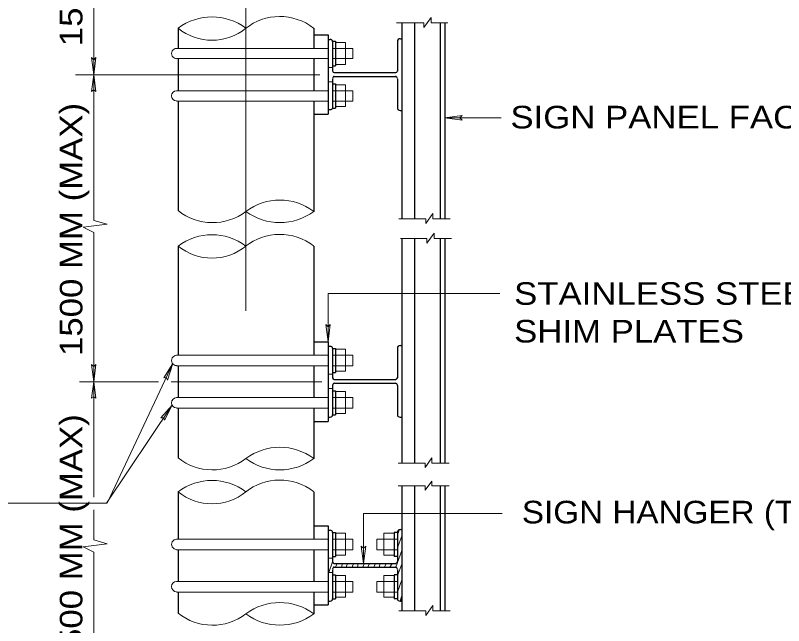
# Model space of a CAD drawing. Extents: x 312601.858 to 312602.699, y 144420.109 to 144420.704.
# Drawn here: x 312602.1613 to 312602.2633, y 144420.5041 to 144420.5851 of the extents above; entities that cross this region are included whole.
import ezdxf
from ezdxf.enums import TextEntityAlignment as Align

# ---------------------------------------------------------------- set-up
doc = ezdxf.new("R2010")
doc.units = 0
doc.header["$LTSCALE"] = 0.0012
doc.linetypes.add('DOT_DASHED', pattern=[7.7, 5, -1.2, 0.3, -1.2])
doc.linetypes.add('MEDIUM_DASHED', pattern=[4.5, 3, -1.5])
doc.layers.add('1', color=7, linetype='Continuous', lineweight=13)
doc.layers.add('2', color=7, linetype='Continuous', lineweight=13)

msp = doc.modelspace()

# ---------------------------------------------------------------- linework, layer by layer
at = {"layer": '1'}
for p, q in [((312602.2155, 144420.5835), (312602.2165, 144420.5848)), ((312602.2165, 144420.5841), (312602.2165, 144420.5848)), ((312602.2119, 144420.5841), (312602.2155, 144420.5841)), ((312602.2155, 144420.5835), (312602.2155, 144420.5841)), ((312602.2165, 144420.5841), (312602.2187, 144420.5841)), ((312602.2028, 144420.5825), (312602.2028, 144420.5736)), ((312602.1827, 144420.5807), (312602.2009, 144420.5807)), ((312602.2051, 144420.5807), (312602.2061, 144420.5807)), ((312602.2061, 144420.5807), (312602.2061, 144420.5794)), ((312602.2009, 144420.5794), (312602.1827, 144420.5794)), ((312602.2061, 144420.5794), (312602.2051, 144420.5794)), ((312602.2038, 144420.5786), (312602.2051, 144420.5786)), ((312602.2028, 144420.5782), (312602.2034, 144420.5782)), ((312602.1693, 144420.5772), (312602.2017, 144420.5772)), ((312602.2028, 144420.5763), (312602.2034, 144420.5763)), ((312602.2038, 144420.5759), (312602.2051, 144420.5759)), ((312602.2051, 144420.573), (312602.2051, 144420.5759)), ((312602.2009, 144420.5751), (312602.1827, 144420.5751)), ((312602.2061, 144420.5751), (312602.2051, 144420.5751)), ((312602.2061, 144420.5737), (312602.2061, 144420.5751)), ((312602.1827, 144420.5737), (312602.2009, 144420.5737)), ((312602.2051, 144420.5737), (312602.2061, 144420.5737)), ((312602.2038, 144420.573), (312602.2051, 144420.573)), ((312602.2258, 144420.5715), (312602.2183, 144420.5715)), ((312602.2122, 144420.5581), (312602.2158, 144420.5581)), ((312602.2158, 144420.5575), (312602.2167, 144420.5588)), ((312602.2158, 144420.5575), (312602.2158, 144420.5581)), ((312602.2167, 144420.5581), (312602.2167, 144420.5588)), ((312602.2167, 144420.5581), (312602.219, 144420.5581)), ((312602.1717, 144420.5563), (312602.1717, 144420.5365)), ((312602.2159, 144420.5549), (312602.2169, 144420.5562)), ((312602.2169, 144420.5555), (312602.2169, 144420.5562)), ((312602.2124, 144420.5555), (312602.2159, 144420.5555)), ((312602.2159, 144420.5549), (312602.2159, 144420.5555)), ((312602.2169, 144420.5555), (312602.2192, 144420.5555)), ((312602.2256, 144420.5482), (312602.2028, 144420.5482)), ((312602.2028, 144420.5482), (312602.2028, 144420.5418)), ((312602.1827, 144420.54), (312602.2009, 144420.54)), ((312602.2051, 144420.54), (312602.2061, 144420.54)), ((312602.2061, 144420.54), (312602.2061, 144420.5386)), ((312602.2009, 144420.5386), (312602.1827, 144420.5386)), ((312602.2061, 144420.5386), (312602.2051, 144420.5386)), ((312602.2028, 144420.5375), (312602.2034, 144420.5375)), ((312602.2038, 144420.5379), (312602.2051, 144420.5379)), ((312602.1698, 144420.5365), (312602.1803, 144420.5365)), ((312602.1717, 144420.5365), (312602.1717, 144420.5212)), ((312602.202, 144420.5365), (312602.182, 144420.5365)), ((312602.2028, 144420.5356), (312602.2034, 144420.5356)), ((312602.2038, 144420.5352), (312602.2051, 144420.5352)), ((312602.2051, 144420.5323), (312602.2051, 144420.5352)), ((312602.2009, 144420.5344), (312602.1827, 144420.5344)), ((312602.2061, 144420.5344), (312602.2051, 144420.5344)), ((312602.2061, 144420.533), (312602.2061, 144420.5344)), ((312602.1827, 144420.533), (312602.2009, 144420.533)), ((312602.2051, 144420.533), (312602.2061, 144420.533)), ((312602.2038, 144420.5323), (312602.2051, 144420.5323)), ((312602.2157, 144420.5251), (312602.2166, 144420.5264)), ((312602.2166, 144420.5257), (312602.2166, 144420.5264)), ((312602.2121, 144420.5257), (312602.2157, 144420.5257)), ((312602.2157, 144420.5251), (312602.2157, 144420.5257)), ((312602.2166, 144420.5257), (312602.2189, 144420.5257)), ((312602.2157, 144420.5221), (312602.2166, 144420.5233)), ((312602.2166, 144420.5227), (312602.2166, 144420.5233)), ((312602.2121, 144420.5227), (312602.2157, 144420.5227)), ((312602.2157, 144420.5221), (312602.2157, 144420.5227)), ((312602.1194, 144420.5204), (312602.1734, 144420.5204)), ((312602.1717, 144420.5195), (312602.1717, 144420.5155)), ((312602.2075, 144420.5124), (312602.2075, 144420.519)), ((312602.2259, 144420.519), (312602.2075, 144420.519)), ((312602.2028, 144420.5174), (312602.2028, 144420.5085)), ((312602.212, 144420.5162), (312602.2123, 144420.5169)), ((312602.1827, 144420.5156), (312602.2009, 144420.5156)), ((312602.2051, 144420.5156), (312602.2061, 144420.5156)), ((312602.2061, 144420.5156), (312602.2061, 144420.5142)), ((312602.2093, 144420.5156), (312602.2093, 144420.5142)), ((312602.2102, 144420.5156), (312602.2093, 144420.5156)), ((312602.212, 144420.5145), (312602.2126, 144420.516)), ((312602.2009, 144420.5142), (312602.1827, 144420.5142)), ((312602.2061, 144420.5142), (312602.2051, 144420.5142)), ((312602.2093, 144420.5142), (312602.2102, 144420.5142)), ((312602.2118, 144420.5119), (312602.2126, 144420.5141)), ((312602.1717, 144420.5139), (312602.1717, 144420.4956)), ((312602.2028, 144420.5131), (312602.2034, 144420.5131)), ((312602.2038, 144420.5135), (312602.2051, 144420.5135)), ((312602.2116, 144420.5135), (312602.2102, 144420.5135)), ((312602.2029, 144420.5112), (312602.2034, 144420.5126)), ((312602.2038, 144420.5119), (312602.204, 144420.5124)), ((312602.2046, 144420.5119), (312602.2047, 144420.5124)), ((312602.2052, 144420.5119), (312602.2054, 144420.5124)), ((312602.206, 144420.5119), (312602.2062, 144420.5124)), ((312602.2067, 144420.5119), (312602.2068, 144420.5124)), ((312602.2074, 144420.5119), (312602.2076, 144420.5124)), ((312602.2081, 144420.5119), (312602.2083, 144420.5124)), ((312602.2089, 144420.5119), (312602.2091, 144420.5124)), ((312602.2096, 144420.5119), (312602.2097, 144420.5124)), ((312602.2103, 144420.5119), (312602.2105, 144420.5124)), ((312602.211, 144420.5119), (312602.2113, 144420.5124)), ((312602.212, 144420.5108), (312602.2126, 144420.5123)), ((312602.2028, 144420.5112), (312602.2034, 144420.5112)), ((312602.2009, 144420.51), (312602.1827, 144420.51)), ((312602.2038, 144420.5108), (312602.2051, 144420.5108)), ((312602.2051, 144420.5079), (312602.2051, 144420.5108)), ((312602.2061, 144420.51), (312602.2051, 144420.51)), ((312602.2061, 144420.5086), (312602.2061, 144420.51)), ((312602.2093, 144420.5086), (312602.2093, 144420.51)), ((312602.2093, 144420.51), (312602.2102, 144420.51)), ((312602.2116, 144420.5108), (312602.2102, 144420.5108)), ((312602.212, 144420.5086), (312602.2126, 144420.5102)), ((312602.1827, 144420.5086), (312602.2009, 144420.5086)), ((312602.2051, 144420.5086), (312602.2061, 144420.5086)), ((312602.2102, 144420.5086), (312602.2093, 144420.5086)), ((312602.2038, 144420.5079), (312602.2051, 144420.5079)), ((312602.2122, 144420.5061), (312602.2158, 144420.5061)), ((312602.2158, 144420.5055), (312602.2167, 144420.5068)), ((312602.2158, 144420.5055), (312602.2158, 144420.5061)), ((312602.2167, 144420.5061), (312602.2167, 144420.5068)), ((312602.2167, 144420.5061), (312602.219, 144420.5061))]:
    msp.add_line(p, q, dxfattribs=at)
at = {"layer": '1', "lineweight": 25}
for p, q in [((312602.1829, 144420.5834), (312602.1829, 144420.5807)), ((312602.2009, 144420.5834), (312602.2009, 144420.5807)), ((312602.2126, 144420.5841), (312602.2126, 144420.5581)), ((312602.2143, 144420.5841), (312602.2143, 144420.5581)), ((312602.2177, 144420.5841), (312602.2177, 144420.5581)), ((312602.2183, 144420.5841), (312602.2183, 144420.5581)), ((312602.2028, 144420.5819), (312602.2031, 144420.5819)), ((312602.2034, 144420.5817), (312602.2034, 144420.5777)), ((312602.2034, 144420.5817), (312602.2038, 144420.5817)), ((312602.2038, 144420.5817), (312602.2038, 144420.5784)), ((312602.212, 144420.5817), (312602.212, 144420.5777)), ((312602.2124, 144420.582), (312602.2126, 144420.582)), ((312602.1829, 144420.5794), (312602.1829, 144420.5751)), ((312602.2009, 144420.5794), (312602.2009, 144420.5751)), ((312602.2034, 144420.5784), (312602.2038, 144420.5784)), ((312602.2036, 144420.5775), (312602.2118, 144420.5775)), ((312602.2034, 144420.5767), (312602.2034, 144420.5728)), ((312602.2036, 144420.577), (312602.2118, 144420.577)), ((312602.212, 144420.5767), (312602.212, 144420.5728)), ((312602.2034, 144420.576), (312602.2038, 144420.576)), ((312602.2038, 144420.576), (312602.2038, 144420.5728)), ((312602.1829, 144420.5737), (312602.1829, 144420.5592)), ((312602.2009, 144420.5737), (312602.2009, 144420.5591)), ((312602.2028, 144420.5726), (312602.2031, 144420.5726)), ((312602.2034, 144420.5728), (312602.2038, 144420.5728)), ((312602.2124, 144420.5725), (312602.2126, 144420.5725)), ((312602.2009, 144420.572), (312602.2028, 144420.572)), ((312602.2126, 144420.5555), (312602.2126, 144420.5257)), ((312602.2143, 144420.5555), (312602.2143, 144420.5257)), ((312602.2177, 144420.5555), (312602.2177, 144420.5257)), ((312602.2183, 144420.5555), (312602.2183, 144420.5257)), ((312602.1829, 144420.5545), (312602.1829, 144420.54)), ((312602.2009, 144420.5545), (312602.2009, 144420.54)), ((312602.2028, 144420.5412), (312602.2031, 144420.5412)), ((312602.2034, 144420.5409), (312602.2034, 144420.537)), ((312602.2034, 144420.5409), (312602.2038, 144420.5409)), ((312602.2038, 144420.5409), (312602.2038, 144420.5377)), ((312602.212, 144420.5409), (312602.212, 144420.537)), ((312602.2124, 144420.5413), (312602.2126, 144420.5413)), ((312602.1829, 144420.5386), (312602.1829, 144420.5344)), ((312602.2009, 144420.5386), (312602.2009, 144420.5344)), ((312602.2034, 144420.5377), (312602.2038, 144420.5377)), ((312602.2036, 144420.5368), (312602.2118, 144420.5368)), ((312602.2034, 144420.536), (312602.2034, 144420.5321)), ((312602.2036, 144420.5363), (312602.2118, 144420.5363)), ((312602.212, 144420.536), (312602.212, 144420.5321)), ((312602.2034, 144420.5353), (312602.2038, 144420.5353)), ((312602.2038, 144420.5353), (312602.2038, 144420.5321)), ((312602.1829, 144420.533), (312602.1829, 144420.5264)), ((312602.2009, 144420.533), (312602.2009, 144420.5263)), ((312602.2028, 144420.5318), (312602.2031, 144420.5318)), ((312602.2034, 144420.5321), (312602.2038, 144420.5321)), ((312602.2124, 144420.5318), (312602.2126, 144420.5318)), ((312602.2009, 144420.5312), (312602.2028, 144420.5312)), ((312602.2126, 144420.5227), (312602.2126, 144420.5061)), ((312602.2143, 144420.5227), (312602.2143, 144420.5061)), ((312602.2177, 144420.5227), (312602.2177, 144420.5061)), ((312602.2183, 144420.5227), (312602.2183, 144420.5061)), ((312602.1829, 144420.5219), (312602.1829, 144420.5156)), ((312602.2009, 144420.5219), (312602.2009, 144420.5156)), ((312602.2028, 144420.5168), (312602.2031, 144420.5168)), ((312602.2034, 144420.5165), (312602.2034, 144420.5126)), ((312602.2034, 144420.5165), (312602.2038, 144420.5165)), ((312602.2038, 144420.5165), (312602.2038, 144420.5133)), ((312602.212, 144420.5165), (312602.2116, 144420.5165)), ((312602.2116, 144420.5165), (312602.2116, 144420.5133)), ((312602.212, 144420.5165), (312602.212, 144420.5126)), ((312602.2124, 144420.5169), (312602.2126, 144420.5169)), ((312602.1829, 144420.5142), (312602.1829, 144420.51)), ((312602.2009, 144420.5142), (312602.2009, 144420.51)), ((312602.2034, 144420.5133), (312602.2038, 144420.5133)), ((312602.212, 144420.5133), (312602.2116, 144420.5133)), ((312602.2036, 144420.5124), (312602.2118, 144420.5124)), ((312602.2034, 144420.5116), (312602.2034, 144420.5077)), ((312602.2036, 144420.5119), (312602.2118, 144420.5119)), ((312602.212, 144420.5116), (312602.212, 144420.5077)), ((312602.2034, 144420.5109), (312602.2038, 144420.5109)), ((312602.2038, 144420.5109), (312602.2038, 144420.5077)), ((312602.212, 144420.5109), (312602.2116, 144420.5109)), ((312602.2116, 144420.5109), (312602.2116, 144420.5077)), ((312602.1829, 144420.5086), (312602.1829, 144420.5058)), ((312602.2009, 144420.5086), (312602.2009, 144420.5057)), ((312602.2124, 144420.5074), (312602.2126, 144420.508)), ((312602.2009, 144420.5069), (312602.2028, 144420.5069)), ((312602.2028, 144420.5074), (312602.2031, 144420.5074)), ((312602.2034, 144420.5077), (312602.2038, 144420.5077)), ((312602.212, 144420.5077), (312602.2116, 144420.5077)), ((312602.2124, 144420.5074), (312602.2126, 144420.5074))]:
    msp.add_line(p, q, dxfattribs=at)
at = {"layer": '1', "linetype": 'MEDIUM_DASHED'}
for p, q in [((312602.2009, 144420.5807), (312602.2028, 144420.5807)), ((312602.2034, 144420.5807), (312602.2051, 144420.5807)), ((312602.2028, 144420.5794), (312602.2009, 144420.5794)), ((312602.2051, 144420.5794), (312602.2034, 144420.5794)), ((312602.2028, 144420.5751), (312602.2009, 144420.5751)), ((312602.2051, 144420.5751), (312602.2034, 144420.5751)), ((312602.2009, 144420.5737), (312602.2028, 144420.5737)), ((312602.2034, 144420.5737), (312602.2051, 144420.5737)), ((312602.2009, 144420.54), (312602.2028, 144420.54)), ((312602.2034, 144420.54), (312602.2051, 144420.54)), ((312602.2028, 144420.5386), (312602.2009, 144420.5386)), ((312602.2051, 144420.5386), (312602.2034, 144420.5386)), ((312602.2028, 144420.5344), (312602.2009, 144420.5344)), ((312602.2051, 144420.5344), (312602.2034, 144420.5344)), ((312602.2009, 144420.533), (312602.2028, 144420.533)), ((312602.2034, 144420.533), (312602.2051, 144420.533)), ((312602.2009, 144420.5156), (312602.2028, 144420.5156)), ((312602.2034, 144420.5156), (312602.2051, 144420.5156)), ((312602.212, 144420.5156), (312602.2102, 144420.5156)), ((312602.2028, 144420.5142), (312602.2009, 144420.5142)), ((312602.2051, 144420.5142), (312602.2034, 144420.5142)), ((312602.2102, 144420.5142), (312602.212, 144420.5142)), ((312602.2028, 144420.51), (312602.2009, 144420.51)), ((312602.2051, 144420.51), (312602.2034, 144420.51)), ((312602.2102, 144420.51), (312602.212, 144420.51)), ((312602.2009, 144420.5086), (312602.2028, 144420.5086)), ((312602.2034, 144420.5086), (312602.2051, 144420.5086)), ((312602.212, 144420.5086), (312602.2102, 144420.5086))]:
    msp.add_line(p, q, dxfattribs=at)
at = {"layer": '1'}
for points in [[(312602.1717, 144420.5965), (312602.1717, 144420.5772), (312602.1717, 144420.5579)], [(312602.2038, 144420.5815), (312602.2051, 144420.5815), (312602.2051, 144420.5786)], [(312602.2038, 144420.5408), (312602.2051, 144420.5408), (312602.2051, 144420.5379)], [(312602.2166, 144420.5227), (312602.2178, 144420.5227), (312602.2189, 144420.5227)], [(312602.2038, 144420.5164), (312602.2051, 144420.5164), (312602.2051, 144420.5135)], [(312602.2116, 144420.5164), (312602.2102, 144420.5164), (312602.2102, 144420.5135)], [(312602.2116, 144420.5079), (312602.2102, 144420.5079), (312602.2102, 144420.5108)]]:
    msp.add_lwpolyline(points, dxfattribs=at)
at = {"layer": '1', "lineweight": 25}
for points in [[(312602.2009, 144420.5825), (312602.2028, 144420.5825), (312602.2028, 144420.572)], [(312602.2009, 144420.5418), (312602.2028, 144420.5418), (312602.2028, 144420.5312)], [(312602.2009, 144420.5174), (312602.2028, 144420.5174), (312602.2028, 144420.5069)]]:
    msp.add_lwpolyline(points, dxfattribs=at)
at = {"layer": '1'}
for points in [[(312602.172, 144420.5795), (312602.1717, 144420.5772), (312602.1714, 144420.5795), (312602.1717, 144420.5792)], [(312602.1714, 144420.575), (312602.1717, 144420.5772), (312602.172, 144420.575), (312602.1717, 144420.5752)], [(312602.2206, 144420.5712), (312602.2183, 144420.5715), (312602.2206, 144420.5718), (312602.2203, 144420.5715)], [(312602.2031, 144420.5441), (312602.2028, 144420.5418), (312602.2025, 144420.5441), (312602.2028, 144420.5438)], [(312602.172, 144420.5388), (312602.1717, 144420.5365), (312602.1714, 144420.5388), (312602.1717, 144420.5385)], [(312602.181, 144420.537), (312602.1822, 144420.5389), (312602.1815, 144420.5367), (312602.1813, 144420.5371)], [(312602.1714, 144420.5343), (312602.1717, 144420.5365), (312602.172, 144420.5343), (312602.1717, 144420.5345)], [(312602.1806, 144420.5317), (312602.1821, 144420.5334), (312602.1811, 144420.5314), (312602.181, 144420.5317)], [(312602.2078, 144420.5147), (312602.2075, 144420.5124), (312602.2072, 144420.5147), (312602.2075, 144420.5144)]]:
    msp.add_lwpolyline(points, close=True, dxfattribs=at)
for centre, radius, start, end in [((312602.1874, 144420.5774), 0.0075, 53.1301, 126.8699), ((312602.1874, 144420.588925), 0.007126, 230.83789, 309.16211), ((312602.182705, 144420.580035), 0.00068, 89.99844, 269.99844), ((312602.182705, 144420.574425), 0.00068, 90.00156, 270), ((312602.1964, 144420.553103), 0.007497, 53.11482, 126.88518), ((312602.187464, 144420.564909), 0.007309, 231.35969, 307.36712), ((312602.1964, 144420.565097), 0.007497, 233.11482, 306.88518), ((312602.1874, 144420.5485), 0.0075, 53.1301, 126.8699), ((312602.1874, 144420.560025), 0.007126, 230.83789, 309.16211), ((312602.182705, 144420.53932), 0.00068, 89.99844, 269.99844), ((312602.182705, 144420.53371), 0.00068, 90.00156, 270), ((312602.1964, 144420.520303), 0.007497, 53.11482, 126.88518), ((312602.187464, 144420.532109), 0.007309, 231.35969, 307.36712), ((312602.1964, 144420.532297), 0.007497, 233.11482, 306.88518), ((312602.1874, 144420.5159), 0.0075, 53.1301, 126.8699), ((312602.1874, 144420.527425), 0.007126, 230.83789, 309.16211), ((312602.182705, 144420.514925), 0.00068, 89.99844, 269.99844), ((312602.182705, 144420.509315), 0.00068, 90.00156, 270), ((312602.1964, 144420.499703), 0.007497, 53.11482, 126.88518), ((312602.187464, 144420.511509), 0.007309, 231.35969, 307.36712), ((312602.1964, 144420.511697), 0.007497, 233.11482, 306.88518)]:
    msp.add_arc(centre, radius, start, end, dxfattribs=at)
at = {"layer": '1', "lineweight": 25}
for centre, radius in [((312602.211775, 144420.537025), 0.000225), ((312602.203105, 144420.532095), 0.000295)]:
    msp.add_arc(centre, radius, 270, 0, dxfattribs=at)
at = {"layer": '1'}
for centre in [(312602.196464, 144420.577599), (312602.196464, 144420.548699), (312602.196464, 144420.516099)]:
    msp.add_ellipse(centre, major_axis=(-0.004613, 0.005762), ratio=0.989423, start_param=4.9552139, end_param=6.2831853, dxfattribs=at)
at = {"layer": '1', "lineweight": 25}
for centre, major_axis, ratio, start_param, end_param in [((312602.203105, 144420.58165), (0.000295, 0), 0.864407, 6.2831853, 7.8539816), ((312602.21237, 144420.58165), (-0.00037, 0), 0.945946, 4.712389, 6.2831853), ((312602.203615, 144420.57774), (0, -0.00024), 0.895833, 4.712389, 6.2831853), ((312602.211775, 144420.57774), (0, -0.00024), 0.9375, 6.2831853, 7.8539816), ((312602.203615, 144420.57672), (0, -0.00028), 0.767857, 3.1415927, 4.712389), ((312602.211775, 144420.57672), (0, 0.00028), 0.803571, 4.712389, 6.2831853), ((312602.203105, 144420.57281), (0.000295, 0), 0.711864, 4.712389, 6.2831853), ((312602.21237, 144420.57281), (-0.00037, 0), 0.837838, 6.2831853, 7.8539816), ((312602.203105, 144420.540935), (0.000295, 0), 0.864407, 6.2831853, 7.8539816), ((312602.21237, 144420.540935), (-0.00037, 0), 0.986486, 4.712389, 6.2831853), ((312602.203615, 144420.537025), (0, -0.000225), 0.955556, 4.712389, 6.2831853), ((312602.203615, 144420.536005), (0, -0.000295), 0.728814, 3.1415927, 4.712389), ((312602.211775, 144420.536005), (0, 0.000295), 0.762712, 4.712389, 6.2831853), ((312602.21237, 144420.532095), (-0.00037, 0), 0.797297, 6.2831853, 7.8539816), ((312602.203105, 144420.51654), (0.000295, 0), 0.864407, 6.148414, 7.8539816), ((312602.21237, 144420.51654), (-0.00037, 0), 0.918919, 4.712389, 6.400294), ((312602.203615, 144420.51263), (0, -0.00023), 0.934783, 4.712389, 6.2831853), ((312602.211775, 144420.51263), (0, -0.00023), 0.978261, 6.2831853, 7.8539816), ((312602.203615, 144420.51161), (0, -0.00029), 0.741379, 3.1415927, 4.712389), ((312602.211775, 144420.51161), (0, 0.00029), 0.775862, 4.712389, 6.2831853), ((312602.203105, 144420.5077), (0, 0.0003), 0.983333, 3.1415927, 4.712389), ((312602.21237, 144420.5077), (-0.00037, 0), 0.810811, 6.2831853, 7.9348857)]:
    msp.add_ellipse(centre, major_axis=major_axis, ratio=ratio, start_param=start_param, end_param=end_param, dxfattribs=at)
at = {"layer": '2', "linetype": 'DOT_DASHED'}
msp.add_line((312602.1919, 144420.6459), (312602.1919, 144420.4762), dxfattribs=at)
at = {"layer": '2'}
for p, q in [((312602.1735, 144420.5204), (312602.1822, 144420.5389)), ((312602.1734, 144420.5204), (312602.1821, 144420.5334))]:
    msp.add_line(p, q, dxfattribs=at)
for points in [[(312602.1717, 144420.5563), (312602.1703, 144420.557), (312602.1735, 144420.5574), (312602.1717, 144420.5579)], [(312602.1717, 144420.5139), (312602.1703, 144420.5146), (312602.1735, 144420.515), (312602.1717, 144420.5155)]]:
    msp.add_lwpolyline(points, dxfattribs=at)

# ---------------------------------------------------------------- texts
at = {"layer": '2', "width": 1.15}
for p in [(312602.1702, 144420.5978), (312602.1702, 144420.5567), (312602.1702, 144420.5154)]:
    msp.add_text('1500 MM (MAX)', height=0.003, rotation=90, dxfattribs=at).set_placement(p, align=Align.CENTER)
at = {"layer": '2'}
for s, width, p in [('SIGN PANEL FACE', 1.15, (312602.24765, 144420.5701)), ('SIGN HANGER (TYP)', 1.1, (312602.25035, 144420.5177))]:
    msp.add_text(s, height=0.003, dxfattribs=dict(at, width=width)).set_placement(p, align=Align.CENTER)
at = {"layer": '2', "width": 1.15}
for s, p in [('STAINLESS STEEL', (312602.2275, 144420.5467)), ('SHIM PLATES', (312602.2275, 144420.5417))]:
    msp.add_text(s, height=0.003, dxfattribs=at).set_placement(p)

doc.saveas('drawing.dxf')
